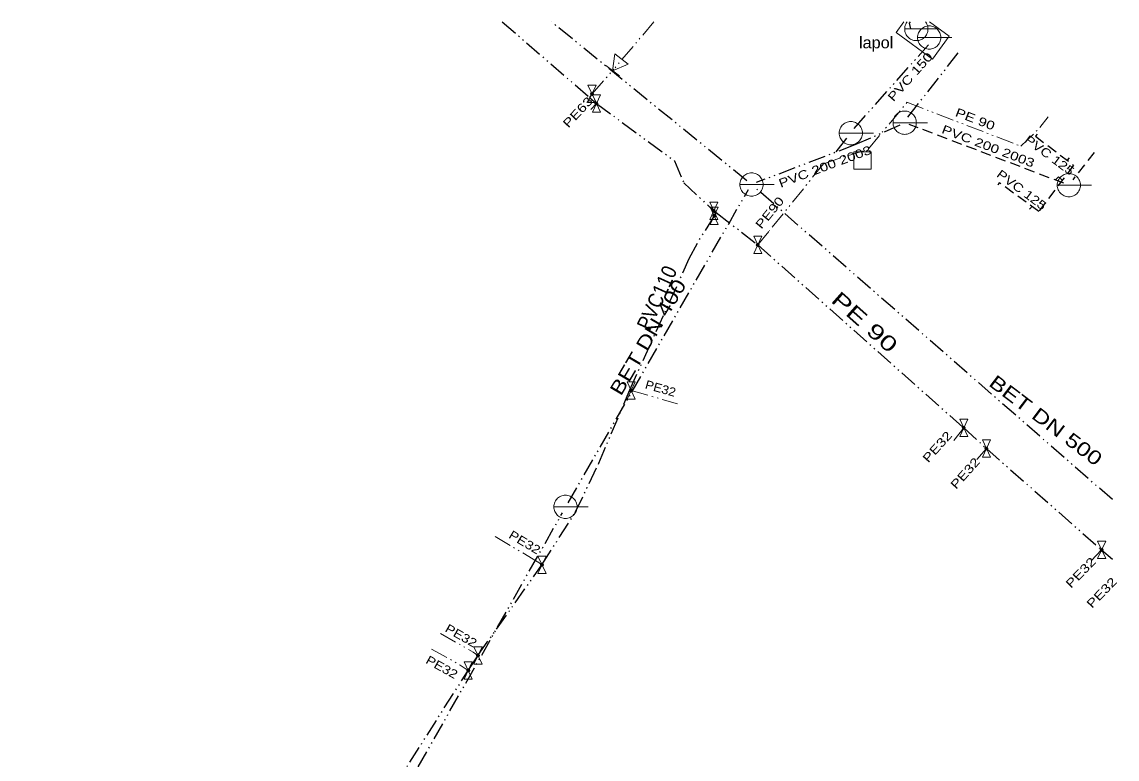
# Model space of a CAD drawing. Extents: x -600643 to -600531, y -1081783 to -1081649.
# Drawn here: x -600626 to -600531.2, y -1081713 to -1081649.2 of the extents above; entities that cross this region are included whole.
import ezdxf
from ezdxf.enums import TextEntityAlignment as Align

# ---------------------------------------------------------------- set-up
doc = ezdxf.new("R2010")
doc.units = 0
doc.header["$LTSCALE"] = 0.3
doc.linetypes.add('DASH_DOUBLE_DOT', pattern=[9.2, 5, -1.2, 0.3, -1.2, 0.3, -1.2])
doc.linetypes.add('MEDIUM_DASHED', pattern=[4.5, 3, -1.5])
for name, color, linetype, lineweight in [('1', 7, 'DASH_DOUBLE_DOT', 25), ('2', 7, 'Continuous', 13), ('41', 7, 'DASH_DOUBLE_DOT', 25), ('42', 7, 'Continuous', 13), ('49', 7, 'Continuous', 13), ('55', 7, 'DASH_DOUBLE_DOT', 25), ('57', 7, 'Continuous', 13), ('58', 7, 'DASH_DOUBLE_DOT', 13)]:
    doc.layers.add(name, color=color, linetype=linetype, lineweight=lineweight)
doc.layers.add('3', color=7, linetype='Continuous')
doc.layers.add('56', color=7, linetype='Continuous')

msp = doc.modelspace()

# ---------------------------------------------------------------- hatches: boundary and pattern name
at = {"layer": '57'}
for points in [[(-600576.5178, -1081655.39, 1), (-600576.7822, -1081655.39, 1)], [(-600576.1378, -1081656.23, 1), (-600576.4022, -1081656.23, 1)], [(-600565.9778, -1081665.51, 1), (-600566.2422, -1081665.51, 1)], [(-600565.9378, -1081665.94, 1), (-600566.2022, -1081665.94, 1)], [(-600562.1678, -1081668.46, 1), (-600562.4322, -1081668.46, 1)], [(-600573.1178, -1081681.06, 1), (-600573.3822, -1081681.06, 1)], [(-600544.3378, -1081684.3, 1), (-600544.6022, -1081684.3, 1)], [(-600542.3778, -1081686.09, 1), (-600542.6422, -1081686.09, 1)], [(-600532.4078, -1081694.86, 1), (-600532.6722, -1081694.86, 1)], [(-600580.8478, -1081696.14, 1), (-600581.1122, -1081696.14, 1)], [(-600586.3878, -1081703.99, 1), (-600586.6522, -1081703.99, 1)], [(-600587.2278, -1081705.28, 1), (-600587.4922, -1081705.28, 1)]]:
    msp.add_hatch(color=256, dxfattribs=at).paths.add_polyline_path(points)

# ---------------------------------------------------------------- linework, layer by layer
at = {"layer": '1'}
for p, q in [((-600563.248, -1081662.905), (-600580.159, -1081649.16)), ((-600578.711, -1081690.777), (-600563.109, -1081663.653)), ((-600531.6, -1081690.506), (-600562.483, -1081663.549)), ((-600625.993, -1081774.075), (-600579.207, -1081691.645))]:
    msp.add_line(p, q, dxfattribs=at)
at = {"layer": '2'}
for p, q in [((-600563.849, -1081663.236), (-600560.873, -1081663.236)), ((-600579.956, -1081691.126), (-600576.98, -1081691.126))]:
    msp.add_line(p, q, dxfattribs=at)
for points in [[(-600562.841, -1081662.228), (-600562.946, -1081662.234), (-600563.05, -1081662.25), (-600563.152, -1081662.278), (-600563.251, -1081662.316), (-600563.345, -1081662.363), (-600563.433, -1081662.421), (-600563.515, -1081662.487), (-600563.59, -1081662.562), (-600563.656, -1081662.644), (-600563.714, -1081662.732), (-600563.761, -1081662.826), (-600563.799, -1081662.925), (-600563.827, -1081663.027), (-600563.843, -1081663.131), (-600563.849, -1081663.236), (-600563.843, -1081663.341), (-600563.827, -1081663.446), (-600563.799, -1081663.548), (-600563.761, -1081663.646), (-600563.714, -1081663.74), (-600563.656, -1081663.829), (-600563.59, -1081663.911), (-600563.515, -1081663.985), (-600563.433, -1081664.051), (-600563.345, -1081664.109), (-600563.251, -1081664.157), (-600563.152, -1081664.195), (-600563.05, -1081664.222), (-600562.946, -1081664.238), (-600562.841, -1081664.244), (-600562.736, -1081664.238), (-600562.631, -1081664.222), (-600562.529, -1081664.195), (-600562.431, -1081664.157), (-600562.337, -1081664.109), (-600562.248, -1081664.051), (-600562.166, -1081663.985), (-600562.092, -1081663.911), (-600562.026, -1081663.829), (-600561.968, -1081663.74), (-600561.92, -1081663.646), (-600561.882, -1081663.548), (-600561.855, -1081663.446), (-600561.839, -1081663.341), (-600561.833, -1081663.236), (-600561.839, -1081663.131), (-600561.855, -1081663.027), (-600561.882, -1081662.925), (-600561.92, -1081662.826), (-600561.968, -1081662.732), (-600562.026, -1081662.644), (-600562.092, -1081662.562), (-600562.166, -1081662.487), (-600562.248, -1081662.421), (-600562.337, -1081662.363), (-600562.431, -1081662.316), (-600562.529, -1081662.278), (-600562.631, -1081662.25), (-600562.736, -1081662.234)], [(-600578.948, -1081690.118), (-600579.053, -1081690.124), (-600579.157, -1081690.14), (-600579.259, -1081690.168), (-600579.358, -1081690.206), (-600579.452, -1081690.253), (-600579.54, -1081690.311), (-600579.622, -1081690.377), (-600579.697, -1081690.452), (-600579.763, -1081690.534), (-600579.821, -1081690.622), (-600579.868, -1081690.716), (-600579.906, -1081690.815), (-600579.934, -1081690.917), (-600579.95, -1081691.021), (-600579.956, -1081691.126), (-600579.95, -1081691.231), (-600579.934, -1081691.336), (-600579.906, -1081691.438), (-600579.868, -1081691.536), (-600579.821, -1081691.63), (-600579.763, -1081691.719), (-600579.697, -1081691.801), (-600579.622, -1081691.875), (-600579.54, -1081691.941), (-600579.452, -1081691.999), (-600579.358, -1081692.047), (-600579.259, -1081692.085), (-600579.157, -1081692.112), (-600579.053, -1081692.128), (-600578.948, -1081692.134), (-600578.843, -1081692.128), (-600578.738, -1081692.112), (-600578.636, -1081692.085), (-600578.538, -1081692.047), (-600578.444, -1081691.999), (-600578.355, -1081691.941), (-600578.273, -1081691.875), (-600578.199, -1081691.801), (-600578.133, -1081691.719), (-600578.075, -1081691.63), (-600578.027, -1081691.536), (-600577.989, -1081691.438), (-600577.962, -1081691.336), (-600577.946, -1081691.231), (-600577.94, -1081691.126), (-600577.946, -1081691.021), (-600577.962, -1081690.917), (-600577.989, -1081690.815), (-600578.027, -1081690.716), (-600578.075, -1081690.622), (-600578.133, -1081690.534), (-600578.199, -1081690.452), (-600578.273, -1081690.377), (-600578.355, -1081690.311), (-600578.444, -1081690.253), (-600578.538, -1081690.206), (-600578.636, -1081690.168), (-600578.738, -1081690.14), (-600578.843, -1081690.124)]]:
    msp.add_lwpolyline(points, close=True, dxfattribs=at)
at = {"layer": '41', "linetype": 'MEDIUM_DASHED'}
for p, q in [((-600535.814, -1081663.127), (-600549.194, -1081658.027)), ((-600533.191, -1081660.451), (-600535.046, -1081662.836))]:
    msp.add_line(p, q, dxfattribs=at)
at = {"layer": '41'}
for p, q in [((-600538.119, -1081658.862), (-600538.278, -1081659.047)), ((-600535.337, -1081660.928), (-600535.523, -1081661.14)), ((-600538.623, -1081665.193), (-600538.782, -1081665.379))]:
    msp.add_line(p, q, dxfattribs=at)
at = {"layer": '41', "linetype": 'MEDIUM_DASHED'}
msp.add_lwpolyline([(-600538.278, -1081659.047), (-600534.966, -1081661.564), (-600537.987, -1081665.564), (-600541.405, -1081663.074), (-600541.537, -1081663.286)], dxfattribs=at)
at = {"layer": '41'}
msp.add_lwpolyline([(-600535.946, -1081662.849), (-600536.264, -1081662.571), (-600536.543, -1081662.822)], dxfattribs=at)
at = {"layer": '42'}
msp.add_line((-600536.382, -1081663.289), (-600533.406, -1081663.289), dxfattribs=at)
msp.add_lwpolyline([(-600535.374, -1081662.281), (-600535.479, -1081662.287), (-600535.583, -1081662.303), (-600535.685, -1081662.331), (-600535.784, -1081662.369), (-600535.878, -1081662.416), (-600535.966, -1081662.474), (-600536.048, -1081662.54), (-600536.123, -1081662.615), (-600536.189, -1081662.697), (-600536.247, -1081662.785), (-600536.294, -1081662.879), (-600536.332, -1081662.978), (-600536.36, -1081663.08), (-600536.376, -1081663.184), (-600536.382, -1081663.289), (-600536.376, -1081663.394), (-600536.36, -1081663.499), (-600536.332, -1081663.601), (-600536.294, -1081663.699), (-600536.247, -1081663.793), (-600536.189, -1081663.882), (-600536.123, -1081663.964), (-600536.048, -1081664.038), (-600535.966, -1081664.104), (-600535.878, -1081664.162), (-600535.784, -1081664.21), (-600535.685, -1081664.248), (-600535.583, -1081664.275), (-600535.479, -1081664.291), (-600535.374, -1081664.297), (-600535.269, -1081664.291), (-600535.164, -1081664.275), (-600535.062, -1081664.248), (-600534.964, -1081664.21), (-600534.87, -1081664.162), (-600534.781, -1081664.104), (-600534.699, -1081664.038), (-600534.625, -1081663.964), (-600534.559, -1081663.882), (-600534.501, -1081663.793), (-600534.453, -1081663.699), (-600534.415, -1081663.601), (-600534.388, -1081663.499), (-600534.372, -1081663.394), (-600534.366, -1081663.289), (-600534.372, -1081663.184), (-600534.388, -1081663.08), (-600534.415, -1081662.978), (-600534.453, -1081662.879), (-600534.501, -1081662.785), (-600534.559, -1081662.697), (-600534.625, -1081662.615), (-600534.699, -1081662.54), (-600534.781, -1081662.474), (-600534.87, -1081662.416), (-600534.964, -1081662.369), (-600535.062, -1081662.331), (-600535.164, -1081662.303), (-600535.269, -1081662.287)], close=True, dxfattribs=at)
at = {"layer": '49'}
for p, q in [((-600549.585, -1081649.77), (-600546.609, -1081649.77)), ((-600548.471, -1081650.512), (-600545.495, -1081650.512)), ((-600550.592, -1081657.882), (-600547.616, -1081657.882)), ((-600555.259, -1081658.783), (-600552.283, -1081658.783))]:
    msp.add_line(p, q, dxfattribs=at)
at = {"layer": '49', "linetype": 'DASH_DOUBLE_DOT', "lineweight": 25}
for p, q in [((-600553.966, -1081658.373), (-600547.526, -1081651.138)), ((-600549.301, -1081657.392), (-600544.822, -1081651.668)), ((-600554.629, -1081659.221), (-600555.609, -1081660.466))]:
    msp.add_line(p, q, dxfattribs=at)
at = {"layer": '49'}
for points in [[(-600547.438, -1081649.16), (-600545.74, -1081650.407), (-600547.186, -1081652.377), (-600550.328, -1081650.07), (-600549.66, -1081649.16)], [(-600549.378, -1081649.16), (-600549.392, -1081649.178), (-600549.45, -1081649.266), (-600549.497, -1081649.36), (-600549.535, -1081649.459), (-600549.563, -1081649.561), (-600549.579, -1081649.665), (-600549.585, -1081649.77), (-600549.579, -1081649.875), (-600549.563, -1081649.98), (-600549.535, -1081650.082), (-600549.497, -1081650.18), (-600549.45, -1081650.274), (-600549.392, -1081650.363), (-600549.326, -1081650.445), (-600549.251, -1081650.519), (-600549.169, -1081650.585), (-600549.081, -1081650.643), (-600548.987, -1081650.691), (-600548.888, -1081650.729), (-600548.786, -1081650.756), (-600548.682, -1081650.772), (-600548.577, -1081650.778), (-600548.472, -1081650.772), (-600548.367, -1081650.756), (-600548.265, -1081650.729), (-600548.167, -1081650.691), (-600548.073, -1081650.643), (-600547.984, -1081650.585), (-600547.902, -1081650.519), (-600547.828, -1081650.445), (-600547.762, -1081650.363), (-600547.704, -1081650.274), (-600547.656, -1081650.18), (-600547.618, -1081650.082), (-600547.591, -1081649.98), (-600547.575, -1081649.875), (-600547.569, -1081649.77), (-600547.575, -1081649.665), (-600547.591, -1081649.561), (-600547.618, -1081649.459), (-600547.656, -1081649.36), (-600547.704, -1081649.266), (-600547.762, -1081649.178), (-600547.776, -1081649.16)]]:
    msp.add_lwpolyline(points, dxfattribs=at)
at = {"layer": '49', "linetype": 'DASH_DOUBLE_DOT', "lineweight": 25}
for points in [[(-600549.047, -1081649.771), (-600549.166, -1081649.274), (-600549.091, -1081649.16)], [(-600549.998, -1081658.11), (-600553.895, -1081659.807), (-600562.431, -1081663.067)]]:
    msp.add_lwpolyline(points, dxfattribs=at)
at = {"layer": '49'}
for points in [[(-600547.463, -1081649.504), (-600547.568, -1081649.51), (-600547.672, -1081649.526), (-600547.774, -1081649.554), (-600547.873, -1081649.592), (-600547.967, -1081649.639), (-600548.055, -1081649.697), (-600548.137, -1081649.763), (-600548.212, -1081649.838), (-600548.278, -1081649.92), (-600548.336, -1081650.008), (-600548.383, -1081650.102), (-600548.421, -1081650.201), (-600548.449, -1081650.303), (-600548.465, -1081650.407), (-600548.471, -1081650.512), (-600548.465, -1081650.617), (-600548.449, -1081650.722), (-600548.421, -1081650.824), (-600548.383, -1081650.922), (-600548.336, -1081651.016), (-600548.278, -1081651.105), (-600548.212, -1081651.187), (-600548.137, -1081651.261), (-600548.055, -1081651.327), (-600547.967, -1081651.385), (-600547.873, -1081651.433), (-600547.774, -1081651.471), (-600547.672, -1081651.498), (-600547.568, -1081651.514), (-600547.463, -1081651.52), (-600547.358, -1081651.514), (-600547.253, -1081651.498), (-600547.151, -1081651.471), (-600547.053, -1081651.433), (-600546.959, -1081651.385), (-600546.87, -1081651.327), (-600546.788, -1081651.261), (-600546.714, -1081651.187), (-600546.648, -1081651.105), (-600546.59, -1081651.016), (-600546.542, -1081650.922), (-600546.504, -1081650.824), (-600546.477, -1081650.722), (-600546.461, -1081650.617), (-600546.455, -1081650.512), (-600546.461, -1081650.407), (-600546.477, -1081650.303), (-600546.504, -1081650.201), (-600546.542, -1081650.102), (-600546.59, -1081650.008), (-600546.648, -1081649.92), (-600546.714, -1081649.838), (-600546.788, -1081649.763), (-600546.87, -1081649.697), (-600546.959, -1081649.639), (-600547.053, -1081649.592), (-600547.151, -1081649.554), (-600547.253, -1081649.526), (-600547.358, -1081649.51)], [(-600549.584, -1081656.874), (-600549.689, -1081656.88), (-600549.793, -1081656.896), (-600549.895, -1081656.924), (-600549.994, -1081656.962), (-600550.088, -1081657.009), (-600550.176, -1081657.067), (-600550.258, -1081657.133), (-600550.333, -1081657.208), (-600550.399, -1081657.29), (-600550.457, -1081657.378), (-600550.504, -1081657.472), (-600550.542, -1081657.571), (-600550.57, -1081657.673), (-600550.586, -1081657.777), (-600550.592, -1081657.882), (-600550.586, -1081657.987), (-600550.57, -1081658.092), (-600550.542, -1081658.194), (-600550.504, -1081658.292), (-600550.457, -1081658.386), (-600550.399, -1081658.475), (-600550.333, -1081658.557), (-600550.258, -1081658.631), (-600550.176, -1081658.697), (-600550.088, -1081658.755), (-600549.994, -1081658.803), (-600549.895, -1081658.841), (-600549.793, -1081658.868), (-600549.689, -1081658.884), (-600549.584, -1081658.89), (-600549.479, -1081658.884), (-600549.374, -1081658.868), (-600549.272, -1081658.841), (-600549.174, -1081658.803), (-600549.08, -1081658.755), (-600548.991, -1081658.697), (-600548.909, -1081658.631), (-600548.835, -1081658.557), (-600548.769, -1081658.475), (-600548.711, -1081658.386), (-600548.663, -1081658.292), (-600548.625, -1081658.194), (-600548.598, -1081658.092), (-600548.582, -1081657.987), (-600548.576, -1081657.882), (-600548.582, -1081657.777), (-600548.598, -1081657.673), (-600548.625, -1081657.571), (-600548.663, -1081657.472), (-600548.711, -1081657.378), (-600548.769, -1081657.29), (-600548.835, -1081657.208), (-600548.909, -1081657.133), (-600548.991, -1081657.067), (-600549.08, -1081657.009), (-600549.174, -1081656.962), (-600549.272, -1081656.924), (-600549.374, -1081656.896), (-600549.479, -1081656.88)], [(-600554.251, -1081657.775), (-600554.356, -1081657.781), (-600554.46, -1081657.797), (-600554.562, -1081657.825), (-600554.661, -1081657.863), (-600554.755, -1081657.91), (-600554.843, -1081657.968), (-600554.925, -1081658.034), (-600555, -1081658.109), (-600555.066, -1081658.191), (-600555.124, -1081658.279), (-600555.171, -1081658.373), (-600555.209, -1081658.472), (-600555.237, -1081658.574), (-600555.253, -1081658.678), (-600555.259, -1081658.783), (-600555.253, -1081658.888), (-600555.237, -1081658.993), (-600555.209, -1081659.095), (-600555.171, -1081659.193), (-600555.124, -1081659.287), (-600555.066, -1081659.376), (-600555, -1081659.458), (-600554.925, -1081659.532), (-600554.843, -1081659.598), (-600554.755, -1081659.656), (-600554.661, -1081659.704), (-600554.562, -1081659.742), (-600554.46, -1081659.769), (-600554.356, -1081659.785), (-600554.251, -1081659.791), (-600554.146, -1081659.785), (-600554.041, -1081659.769), (-600553.939, -1081659.742), (-600553.841, -1081659.704), (-600553.747, -1081659.656), (-600553.658, -1081659.598), (-600553.576, -1081659.532), (-600553.502, -1081659.458), (-600553.436, -1081659.376), (-600553.378, -1081659.287), (-600553.33, -1081659.193), (-600553.292, -1081659.095), (-600553.265, -1081658.993), (-600553.249, -1081658.888), (-600553.243, -1081658.783), (-600553.249, -1081658.678), (-600553.265, -1081658.574), (-600553.292, -1081658.472), (-600553.33, -1081658.373), (-600553.378, -1081658.279), (-600553.436, -1081658.191), (-600553.502, -1081658.109), (-600553.576, -1081658.034), (-600553.658, -1081657.968), (-600553.747, -1081657.91), (-600553.841, -1081657.863), (-600553.939, -1081657.825), (-600554.041, -1081657.797), (-600554.146, -1081657.781)]]:
    msp.add_lwpolyline(points, close=True, dxfattribs=at)
at = {"layer": '55'}
for p, q in [((-600584.418, -1081649.16), (-600576.86, -1081655.7)), ((-600576.86, -1081655.7), (-600576.27, -1081656.23)), ((-600565.89, -1081665.65), (-600562.3, -1081668.46)), ((-600562.3, -1081668.46), (-600544.47, -1081684.3)), ((-600544.47, -1081684.3), (-600542.51, -1081686.09)), ((-600542.51, -1081686.09), (-600532.54, -1081694.86)), ((-600532.54, -1081694.86), (-600531.6, -1081695.663)), ((-600586.52, -1081703.99), (-600580.98, -1081696.14))]:
    msp.add_line(p, q, dxfattribs=at)
for points in [[(-600576.27, -1081656.23), (-600569.51, -1081661.19), (-600568.7, -1081663.1), (-600566.11, -1081665.51), (-600565.89, -1081665.65), (-600566.07, -1081665.94), (-600567.24, -1081667.8)], [(-600573.38, -1081681.01), (-600568.23, -1081669.64), (-600567.24, -1081667.8)], [(-600580.98, -1081696.14), (-600578.1, -1081691.62), (-600576.06, -1081687.36), (-600573.38, -1081681.01)], [(-600594.47, -1081716.47), (-600593.91, -1081715.57), (-600587.36, -1081705.28), (-600586.52, -1081703.99)]]:
    msp.add_lwpolyline(points, dxfattribs=at)
at = {"layer": '57'}
for points in [[(-600577, -1081654.64), (-600576.3, -1081654.64), (-600577, -1081656.14), (-600576.3, -1081656.14)], [(-600576.62, -1081655.48), (-600575.92, -1081655.48), (-600576.62, -1081656.98), (-600575.92, -1081656.98)], [(-600553.98, -1081661.9), (-600552.48, -1081661.9), (-600552.48, -1081660.4), (-600553.98, -1081660.4)], [(-600566.46, -1081664.76), (-600565.76, -1081664.76), (-600566.46, -1081666.26), (-600565.76, -1081666.26)], [(-600566.42, -1081665.19), (-600565.72, -1081665.19), (-600566.42, -1081666.69), (-600565.72, -1081666.69)], [(-600562.65, -1081667.71), (-600561.95, -1081667.71), (-600562.65, -1081669.21), (-600561.95, -1081669.21)], [(-600573.6, -1081680.31), (-600572.9, -1081680.31), (-600573.6, -1081681.81), (-600572.9, -1081681.81)], [(-600544.82, -1081683.55), (-600544.12, -1081683.55), (-600544.82, -1081685.05), (-600544.12, -1081685.05)], [(-600542.86, -1081685.34), (-600542.16, -1081685.34), (-600542.86, -1081686.84), (-600542.16, -1081686.84)], [(-600532.89, -1081694.11), (-600532.19, -1081694.11), (-600532.89, -1081695.61), (-600532.19, -1081695.61)], [(-600581.33, -1081695.39), (-600580.63, -1081695.39), (-600581.33, -1081696.89), (-600580.63, -1081696.89)], [(-600586.87, -1081703.24), (-600586.17, -1081703.24), (-600586.87, -1081704.74), (-600586.17, -1081704.74)], [(-600587.71, -1081704.53), (-600587.01, -1081704.53), (-600587.71, -1081706.03), (-600587.01, -1081706.03)]]:
    msp.add_lwpolyline(points, close=True, dxfattribs=at)
for centre in [(-600576.65, -1081655.39), (-600576.27, -1081656.23), (-600566.11, -1081665.51), (-600566.07, -1081665.94), (-600562.3, -1081668.46), (-600573.25, -1081681.06), (-600544.47, -1081684.3), (-600542.51, -1081686.09), (-600532.54, -1081694.86), (-600580.98, -1081696.14), (-600586.52, -1081703.99), (-600587.36, -1081705.28)]:
    msp.add_circle(centre, 0.1322, dxfattribs=at)
at = {"layer": '58', "linetype": 'Continuous'}
msp.add_line((-600574.281, -1081653.826), (-600575.458, -1081652.935), dxfattribs=at)
at = {"layer": '58'}
for p, q in [((-600576.27, -1081656.23), (-600576.76, -1081656.75)), ((-600537.178, -1081657.385), (-600537.88, -1081658.31)), ((-600553.022, -1081660.283), (-600554.94, -1081660.86)), ((-600556.61, -1081661.44), (-600554.963, -1081660.868)), ((-600556.61, -1081661.44), (-600561.29, -1081667.23)), ((-600562.3, -1081668.46), (-600561.29, -1081667.23)), ((-600545.33, -1081685.38), (-600544.47, -1081684.3)), ((-600542.51, -1081686.09), (-600543.35, -1081687.03)), ((-600532.54, -1081694.86), (-600533.45, -1081695.81))]:
    msp.add_line(p, q, dxfattribs=at)
for points in [[(-600571.292, -1081649.16), (-600574.757, -1081653.24), (-600574.927, -1081653.45)], [(-600576.86, -1081655.7), (-600576.65, -1081655.39), (-600574.87, -1081653.38)], [(-600552.71, -1081660.15), (-600549.39, -1081656.12), (-600539.52, -1081659.92), (-600537.88, -1081658.31)], [(-600573.38, -1081681.01), (-600573.25, -1081681.06), (-600569.243, -1081682.212)], [(-600585.033, -1081693.695), (-600581.34, -1081695.89), (-600580.98, -1081696.14)], [(-600589.761, -1081702.084), (-600586.93, -1081703.7), (-600586.52, -1081703.99)], [(-600590.534, -1081703.447), (-600588.05, -1081704.83), (-600587.36, -1081705.28)]]:
    msp.add_lwpolyline(points, dxfattribs=at)
at = {"layer": '58', "linetype": 'Continuous'}
msp.add_lwpolyline([(-600574.687, -1081651.915), (-600573.509, -1081652.806), (-600574.87, -1081653.38)], close=True, dxfattribs=at)

# ---------------------------------------------------------------- texts
at = {"layer": '3'}
for s, rotation, width, p in [('BET DN 400', 59.522, 1.25, (-600571.2865, -1081676.7413)), ('BET DN 500', 322.794, 1.3, (-600537.7323, -1081684.1233))]:
    msp.add_text(s, height=1.2, rotation=rotation, dxfattribs=dict(at, width=width)).set_placement(p, align=Align.CENTER)
at = {"layer": '41'}
for s, rotation, width, p in [('PVC 200 2003', 339.159, 1.3, (-600546.453, -1081658.753)), ('PVC 125', 323.293, 1.25, (-600539.288, -1081659.501)), ('PVC 125', 323.293, 1.25, (-600541.699, -1081662.492))]:
    msp.add_text(s, height=0.75, rotation=rotation, dxfattribs=dict(at, width=width)).set_placement(p)
at = {"layer": '49', "width": 1.05}
msp.add_text('lapol', height=1, dxfattribs=at).set_placement((-600553.539, -1081651.444))
at = {"layer": '49', "width": 1.3}
for s, rotation, p in [('PVC 150', 48.353, (-600550.565, -1081656.113)), ('PVC 200 2003', 20.617, (-600560.319, -1081663.523))]:
    msp.add_text(s, height=0.75, rotation=rotation, dxfattribs=at).set_placement(p)
at = {"layer": '56', "width": 0.9}
msp.add_text('PVC110', height=1.3, rotation=65.632, dxfattribs=at).set_placement((-600571.642, -1081675.96))
at = {"layer": '56', "width": 1.45}
msp.add_text('PE 90', height=1.3, rotation=318.382, dxfattribs=at).set_placement((-600553.4802, -1081675.6266), align=Align.CENTER)
at = {"layer": '58', "width": 1.3}
for s, rotation, p in [('PE63', 46.701, (-600577.6072, -1081657.2322)), ('PE90', 50.609, (-600560.982, -1081665.9095)), ('PE32', 47.997, (-600546.487, -1081686.1819)), ('PE32', 48.368, (-600544.0738, -1081688.4686)), ('PE32', 45.864, (-600534.084, -1081697.0806)), ('PE32', 45.864, (-600532.267, -1081698.8186))]:
    msp.add_text(s, height=0.75, rotation=rotation, dxfattribs=at).set_placement(p, align=Align.CENTER)
at = {"layer": '58'}
for s, rotation, width, p in [('PE 90', 338.943, 1.3, (-600545.274, -1081657.282)), ('PE32', 343.957, 1.1, (-600572.116, -1081680.866)), ('PE32', 329.27, 1.2, (-600583.929, -1081693.769)), ('PE32', 330.28, 1.2, (-600589.441, -1081701.874)), ('PE32', 330.898, 1.2, (-600591.114, -1081704.613))]:
    msp.add_text(s, height=0.75, rotation=rotation, dxfattribs=dict(at, width=width)).set_placement(p)

doc.saveas('drawing.dxf')
